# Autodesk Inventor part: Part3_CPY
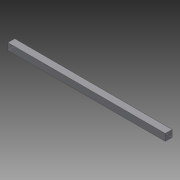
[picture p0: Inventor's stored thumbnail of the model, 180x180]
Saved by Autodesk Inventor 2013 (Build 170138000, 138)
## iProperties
Created: 2013-06
Part Number: Part3_CPY
Material: Generic
Document SubType Name: Modeling
Designer: jpfenske
Mass: 1272.05 g
Surface Area: 1364.51 cm^2
Volume: 1272.05 cm^3
Density: 1 g/cm^3
Author: jpfenske
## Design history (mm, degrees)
sketch "Sketch1"
  geometry: L1 (-414.892, 325.462)-(461.408, 325.462); L2 (461.408, 325.462)-(461.408, 287.362); L3 (461.408, 287.362)-(-414.892, 287.362); L4 (-414.892, 287.362)-(-414.892, 325.462); 1 further point
  constraints: 8 end point, 2 parallel, 1 horizontal, 1 perpendicular
  dimensions: "d0" = 876.3 distance of L1.start L1.end; "d1" = 38.1 distance of L1.end L2.end
extrude "Extrusion1" new body sketch "Sketch1" distance "d2" = 38.1; taper "d3" = 0 deg
body "Solid1"
